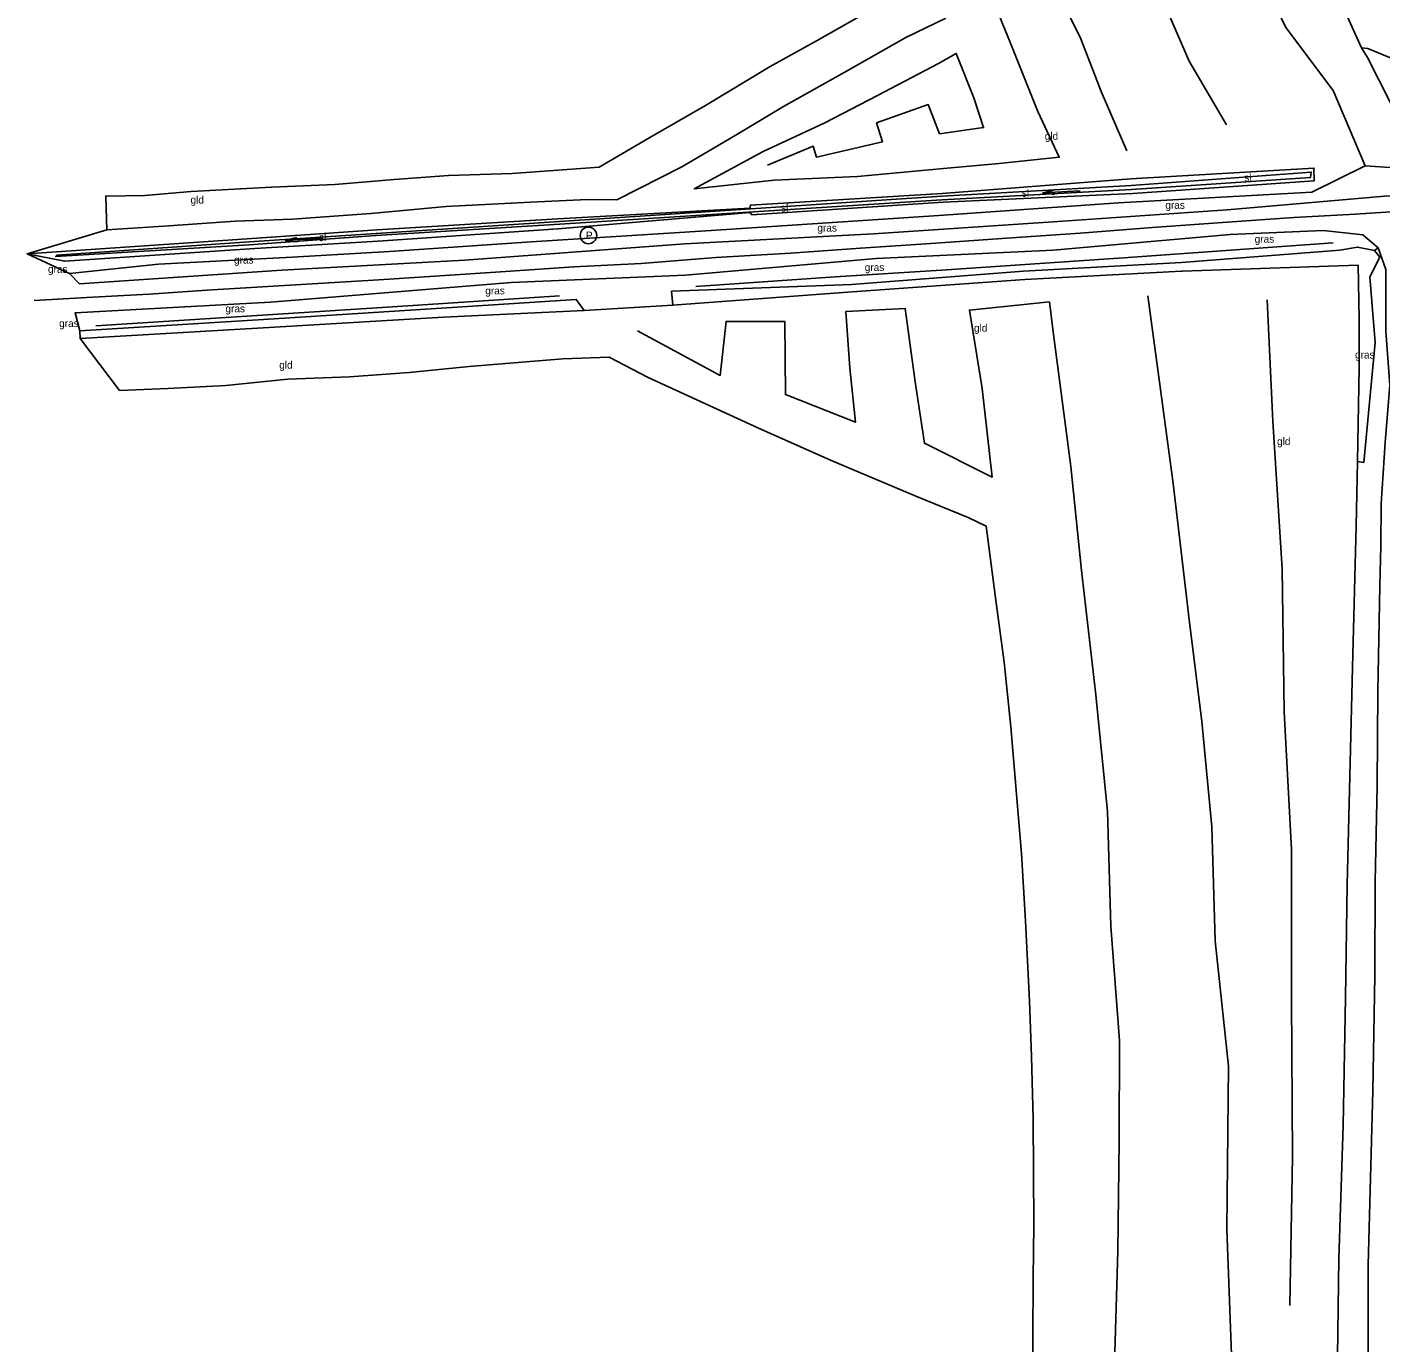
# Model space of a CAD drawing. Extents: x 154825 to 158680, y 370717 to 378075.
# Drawn here: x 156426.4 to 156606.6, y 375862.1 to 376037.2 of the extents above; entities that cross this region are included whole.
import ezdxf

# ---------------------------------------------------------------- set-up
doc = ezdxf.new("R2010")
doc.units = 0
for name, color, linetype in [('cultuurscheiding', 7, 'Continuous'), ('grasland_productiegrasl(vs)', 7, 'Continuous'), ('grazige vegetatie(vs)', 7, 'Continuous'), ('hoogteverschillijn', 7, 'Continuous'), ('insteek sloot', 7, 'Continuous'), ('maaiveldlijn algemeen - bomenrij', 7, 'Continuous'), ('maaiveldlijn algemeen - onverhard', 7, 'Continuous'), ('paal', 7, 'Continuous'), ('Sloot bodem', 7, 'Continuous'), ('sloot(vs)', 7, 'Continuous'), ('stroomrichting  watergangen', 7, 'Continuous'), ('talud(boven)', 7, 'Continuous'), ('talud(onder)', 7, 'Continuous'), ('vlak_Bos', 7, 'Continuous'), ('vlak_Grasland', 7, 'Continuous'), ('vlak_Grazige_vegetatie', 7, 'Continuous')]:
    doc.layers.add(name, color=color, linetype=linetype)

msp = doc.modelspace()

# ---------------------------------------------------------------- linework, layer by layer
at = {"layer": 'cultuurscheiding'}
for points in [[(156604.54, 376018.73), (156612.4, 376018.17)], [(156500.54, 375999.48), (156512.36, 376000.18)]]:
    msp.add_lwpolyline(points, dxfattribs=at)
at = {"layer": 'hoogteverschillijn'}
for points in [[(156572.81, 376020.7), (156569.38, 376028.63), (156566.66, 376035.61), (156562.66, 376043.74), (156558.89, 376051.97), (156554.33, 376061.88), (156550.91, 376068.69), (156549.14, 376076.18), (156546.72, 376083.8), (156543.62, 376095.48), (156540.86, 376103.26), (156537.96, 376111.44), (156532.62, 376123.33), (156528.05, 376133.6), (156524.15, 376142.59), (156520.35, 376150.68), (156516.56, 376158.36), (156513.06, 376167.53), (156508.88, 376177.28)], [(156521.01, 376174.48), (156526.43, 376162.47), (156529.26, 376156.81), (156535.53, 376142.49), (156540.79, 376129.18), (156547.42, 376112.95), (156551.02, 376105.12), (156555.68, 376094.87), (156558.92, 376084.45), (156563.58, 376070.67), (156570.02, 376056.98), (156576.17, 376044.06), (156581.09, 376032.64), (156586.08, 376024.16)], [(156554.59, 376041.68), (156557.33, 376035.04), (156560.94, 376025.97), (156563.79, 376019.86), (156555.81, 376019.01), (156548.37, 376018.35), (156536.94, 376017.28), (156525.83, 376016.81), (156515.22, 376015.65), (156524.37, 376020.63), (156532.58, 376024.45), (156539.59, 376028.08), (156547.73, 376032.32), (156550.09, 376033.68), (156552.45, 376027.78), (156553.73, 376023.81), (156547.86, 376022.99), (156546.36, 376026.87), (156539.49, 376024.42), (156540.26, 376021.89), (156531.48, 376019.88), (156531.05, 376021.33), (156524.96, 376018.8)], [(156539.14, 376039.72), (156531.59, 376035.39), (156525.3, 376031.93), (156516.7, 376026.74), (156509.3, 376022.5), (156502.55, 376018.53), (156490.99, 376017.72), (156482.51, 376017.43), (156475.25, 376016.91), (156467.36, 376016.23), (156458.94, 376015.89), (156448.24, 376015.32), (156442.1, 376014.76), (156436.88, 376014.69), (156437.02, 376010.22), (156445.26, 376010.73), (156454.1, 376011.34), (156461.72, 376011.62), (156472.16, 376012.38), (156482.17, 376013.31), (156493.42, 376013.88), (156501, 376014.22), (156504.89, 376014.19), (156513.54, 376018.57), (156520.67, 376022.77), (156527.08, 376026.62), (156535.16, 376031.13), (156543.38, 376035.78), (156548.72, 376038.38)], [(156604.88, 376034.31), (156610.79, 376031.88), (156617.32, 376029.23), (156621.46, 376027.63), (156624.69, 376026.73), (156632.63, 376026.83), (156642.28, 376027.82), (156651.67, 376028.35), (156659.22, 376028.61), (156666.15, 376029.34), (156673.91, 376029.82), (156685.81, 376030.47), (156685.94, 376026.48), (156678.99, 376025.48), (156670.4, 376025.46), (156664.83, 376024.91), (156657.65, 376024.69), (156650.29, 376024.51), (156641.83, 376024.02), (156632.93, 376023.17), (156624.09, 376022.6), (156617.93, 376022.16), (156612.67, 376024.46)], [(156427.36, 376000.79), (156435.16, 376001.23), (156442.65, 376001.65), (156450.32, 376002.19), (156473.24, 376003.53), (156480.69, 376004.02), (156490.08, 376004.65), (156499.18, 376005.27), (156508.15, 376005.73), (156518.1, 376006.5), (156528.04, 376007.11), (156537.36, 376007.78), (156547.35, 376008.42), (156556.81, 376009.08), (156566.6, 376009.74), (156576.22, 376010.52), (156585.55, 376011.16), (156595.04, 376011.84), (156603.2, 376012.28), (156612.73, 376012.91)], [(156575.57, 376001.43), (156577.26, 375988.97), (156578.96, 375976.43), (156581.11, 375958.35), (156582.78, 375944.78), (156584.12, 375930.78), (156584.54, 375915.59), (156586.31, 375898.91), (156586.09, 375877.23), (156586.8, 375858.13), (156586.79, 375839.49), (156586.62, 375822.23), (156586.22, 375803.72), (156585.44, 375775.48), (156585.17, 375755.87), (156585.34, 375731.27), (156585.3, 375705.98), (156584.63, 375684.03)], [(156571.14, 375859.31), (156571.58, 375874.28), (156571.79, 375888.99), (156571.83, 375902.32), (156570.66, 375917.55), (156570.23, 375932.86), (156568.61, 375948.72), (156566.77, 375964.85), (156565.34, 375978.7), (156562.97, 375996.65), (156562.5, 376000.6), (156551.83, 375999.53), (156553.54, 375989.11), (156554.87, 375977.3), (156545.86, 375981.8), (156544.64, 375989.98), (156543.28, 375999.74), (156535.38, 375999.32), (156535.93, 375991.8), (156536.66, 375984.6), (156527.35, 375988.28), (156527.26, 375998.01), (156519.45, 375998.01), (156518.68, 375990.83), (156507.68, 375996.78)], [(156591.46, 376000.9), (156592.25, 375984.75), (156593.49, 375965.08), (156593.73, 375946.05), (156594.73, 375927.73), (156594.73, 375907.83), (156594.85, 375886.86), (156594.5, 375867.08)], [(156438.73, 375988.81), (156445.14, 375989.08), (156452.86, 375989.49), (156461.12, 375990.35), (156469.31, 375990.63), (156477.25, 375991.22), (156485.27, 375992.02), (156497.7, 375993.04), (156503.88, 375993.25), (156509.09, 375990.55), (156523.67, 375983.84), (156533.33, 375979.56), (156544.73, 375974.78), (156551.67, 375971.92), (156554.06, 375970.77), (156555.39, 375960.55), (156556.48, 375952.68), (156557.35, 375944.05), (156558.33, 375932.44), (156558.79, 375927.23), (156559.32, 375918.22), (156559.85, 375907.59), (156560.1, 375900.22), (156560.34, 375891.92), (156560.42, 375877.81), (156560.33, 375870.69), (156560.3, 375862.63), (156560.23, 375856.26)]]:
    msp.add_lwpolyline(points, dxfattribs=at)
at = {"layer": 'insteek sloot'}
msp.add_lwpolyline([(156597.7, 376018.42), (156573.34, 376017), (156548.2, 376015.05), (156522.69, 376013.5), (156522.61, 376013.07), (156497.05, 376011.67), (156473.02, 376010.19), (156454.42, 376008.93), (156426.41, 376007.02), (156431.41, 376006.03), (156456.72, 376007.74), (156473.14, 376008.68), (156497.04, 376010.32), (156522.65, 376012.52), (156522.9, 376012.2), (156548.36, 376013.87), (156573.59, 376015.05), (156597.71, 376016.71), (156597.7, 376018.42)], dxfattribs=at)
at = {"layer": 'maaiveldlijn algemeen - bomenrij'}
for points in [[(156604.85, 376033.15), (156604.03, 376034.4), (156598.81, 376046.03), (156593.52, 376057.34), (156586.98, 376071.77), (156581.55, 376083.58), (156576.24, 376095.35), (156568.66, 376112.12), (156562.27, 376126.6), (156550.14, 376152.66), (156543.83, 376166.91), (156537.32, 376180.85), (156530.37, 376196.59), (156518.98, 376222.43), (156509.87, 376242.4), (156507.27, 376248.14), (156501.91, 376260.01), (156498.71, 376267.58)], [(156503.91, 376232.79), (156504.98, 376231.61), (156514.5, 376210.59), (156527.1, 376182.74), (156537.65, 376159.52), (156549.71, 376132.58), (156562.03, 376105.32), (156575.26, 376075.98), (156593.98, 376037.13), (156600.26, 376028.74), (156604.54, 376018.73), (156597.43, 376015.23), (156571.68, 376013.78), (156547.77, 376012.12), (156517.45, 376010.13), (156493.51, 376008.61), (156474.64, 376007.3), (156461.67, 376006.58), (156443.92, 376005.62), (156432.05, 376004.41)], [(156693.04, 376021.31), (156667.6, 376019.69), (156643.66, 376018.26), (156619.44, 376016.89), (156612.4, 376018.17), (156604.85, 376033.15), (156604.03, 376034.4)], [(156600.27, 376008.48), (156572.37, 376006.48), (156548.11, 376004.85), (156533.98, 376003.94), (156515.43, 376002.64)], [(156497.26, 376001.44), (156475.05, 375999.96), (156435.54, 375997.41)], [(156603.48, 375979.36), (156603.32, 375970.76), (156602.84, 375951.94), (156602.12, 375923.05), (156601.9, 375908.04), (156601.61, 375891.01), (156601, 375873.29), (156600.65, 375847.27), (156600.46, 375831.64), (156600.18, 375815.71), (156599.28, 375767.14), (156599.09, 375748.37), (156598.64, 375715.86), (156598.42, 375698.91), (156598.97, 375673.82)]]:
    msp.add_lwpolyline(points, dxfattribs=at)
at = {"layer": 'maaiveldlijn algemeen - onverhard'}
for points in [[(156433.39, 376003.01), (156460.31, 376004.82), (156484.66, 376006.15), (156513.94, 376008.36), (156539.09, 376009.68), (156563.01, 376011.28), (156586.14, 376012.86), (156607.15, 376014.69), (156622.62, 376015.22), (156644.34, 376016.34), (156693.74, 376020.07)], [(156432.8, 375999.17), (156458.8, 376000.56), (156490.83, 376003.18), (156514.06, 376004.16), (156539.42, 376006.39), (156562.97, 376007.51), (156586.55, 376009.57), (156598.96, 376010.13), (156604.22, 376009.52), (156606.24, 376007.8), (156607.29, 376004.92), (156607.27, 375996.72), (156607.79, 375989.55), (156607.16, 375981.92)], [(156604.91, 375859.72), (156604.93, 375872.44), (156605.52, 375895.64), (156605.8, 375910.92), (156605.85, 375923.43), (156606.12, 375936.28), (156606.21, 375948.78), (156606.49, 375962.82), (156606.61, 375968.16), (156606.64, 375973.76), (156607.16, 375981.92)]]:
    msp.add_lwpolyline(points, dxfattribs=at)
at = {"layer": 'paal'}
msp.add_circle((156501.13, 376009.46), 1.1, dxfattribs=at)
at = {"layer": 'Sloot bodem'}
msp.add_lwpolyline([(156597.34, 376017.89), (156573.36, 376016.11), (156548.17, 376014.68), (156496.61, 376011.28), (156472.89, 376009.71), (156455.97, 376008.6), (156430.37, 376006.82), (156430.2, 376006.65), (156455.97, 376008.2), (156472.82, 376009.45), (156496.63, 376010.89), (156548.17, 376014.18), (156573.43, 376015.57), (156597.23, 376017.17), (156597.34, 376017.89)], dxfattribs=at)
at = {"layer": 'stroomrichting  watergangen'}
for p, q in [((156561.59, 376015.14), (156563.13, 376015.49)), ((156566.58, 376015.37), (156561.59, 376015.14)), ((156561.61, 376015.13), (156563.18, 376014.92)), ((156460.78, 376008.82), (156462.32, 376009.16)), ((156465.77, 376009.05), (156460.78, 376008.82)), ((156460.8, 376008.8), (156462.36, 376008.6))]:
    msp.add_line(p, q, dxfattribs=at)
at = {"layer": 'talud(boven)'}
for points in [[(156512.19, 376002.03), (156536.15, 376002.92), (156559.04, 376004.72), (156580.08, 376005.86), (156601.14, 376007.49), (156603.52, 376007.91), (156605.75, 376007.47), (156606.48, 376006.57), (156605.16, 376003.94), (156605.85, 375995.23), (156604.34, 375979.25)], [(156433.44, 375996.78), (156458.6, 375998.32), (156481.56, 375999.8), (156499.5, 376000.91)]]:
    msp.add_lwpolyline(points, dxfattribs=at)
at = {"layer": 'talud(onder)'}
for points in [[(156512.36, 376000.18), (156536.23, 376001.97), (156559.21, 376003.6), (156580.06, 376004.7), (156580.15, 376004.7), (156603.6, 376005.48), (156603.7, 375998.36), (156603.73, 375991.89), (156603.48, 375979.36)], [(156512.36, 376000.18), (156512.19, 376002.03)], [(156500.54, 375999.48), (156499.5, 376000.91)], [(156433.44, 375996.78), (156433.46, 375995.74), (156458.57, 375997.2), (156481.84, 375998.59), (156500.54, 375999.48)], [(156604.34, 375979.25), (156603.48, 375979.36)]]:
    msp.add_lwpolyline(points, dxfattribs=at)
at = {"layer": 'vlak_Bos'}
for points in [[(156537.32, 376180.85), (156543.83, 376166.91), (156550.14, 376152.66), (156562.27, 376126.6), (156568.66, 376112.12), (156576.24, 376095.35), (156581.55, 376083.58), (156586.98, 376071.77), (156593.52, 376057.34), (156598.81, 376046.03), (156604.03, 376034.4), (156604.85, 376033.15), (156612.4, 376018.17), (156604.54, 376018.73), (156600.26, 376028.74), (156593.98, 376037.13), (156575.26, 376075.98), (156562.03, 376105.32), (156549.71, 376132.58), (156537.65, 376159.52), (156527.1, 376182.74)], [(156600.65, 375847.27), (156601, 375873.29), (156601.61, 375891.01), (156601.9, 375908.04), (156602.12, 375923.05), (156602.84, 375951.94), (156603.32, 375970.76), (156603.48, 375979.36), (156604.34, 375979.25), (156605.85, 375995.23), (156605.16, 376003.94), (156606.48, 376006.57), (156605.75, 376007.47), (156606.24, 376007.8), (156607.29, 376004.92)], [(156606.64, 375973.76), (156606.61, 375968.16), (156606.49, 375962.82), (156606.21, 375948.78), (156606.12, 375936.28), (156605.85, 375923.43), (156605.8, 375910.92), (156605.52, 375895.64), (156604.93, 375872.44), (156604.91, 375859.72)]]:
    msp.add_lwpolyline(points, dxfattribs=at)
at = {"layer": 'vlak_Grasland'}
for points in [[(156575.26, 376075.98), (156593.98, 376037.13), (156600.26, 376028.74), (156604.54, 376018.73), (156597.43, 376015.23), (156571.68, 376013.78), (156547.77, 376012.12), (156517.45, 376010.13), (156493.51, 376008.61), (156474.64, 376007.3), (156461.67, 376006.58), (156443.92, 376005.62), (156432.05, 376004.41), (156426.41, 376007.02), (156431.41, 376006.03), (156456.72, 376007.74), (156473.14, 376008.68), (156497.04, 376010.32), (156522.65, 376012.52), (156522.9, 376012.2), (156548.36, 376013.87), (156573.59, 376015.05), (156597.71, 376016.71), (156597.7, 376018.42), (156573.34, 376017), (156548.2, 376015.05), (156522.69, 376013.5), (156522.61, 376013.07), (156497.05, 376011.67), (156473.02, 376010.19), (156454.42, 376008.93), (156426.41, 376007.02), (156437.02, 376010.22), (156436.88, 376014.69), (156442.1, 376014.76), (156448.24, 376015.32), (156458.94, 376015.89), (156467.36, 376016.23), (156475.25, 376016.91), (156482.51, 376017.43), (156490.99, 376017.72), (156502.55, 376018.53), (156509.3, 376022.5), (156516.7, 376026.74), (156525.3, 376031.93), (156531.59, 376035.39), (156539.14, 376039.72)], [(156560.23, 375856.26), (156560.3, 375862.63), (156560.33, 375870.69), (156560.42, 375877.81), (156560.34, 375891.92), (156560.1, 375900.22), (156559.85, 375907.59), (156559.32, 375918.22), (156558.79, 375927.23), (156558.33, 375932.44), (156557.35, 375944.05), (156556.48, 375952.68), (156555.39, 375960.55), (156554.06, 375970.77), (156551.67, 375971.92), (156544.73, 375974.78), (156533.33, 375979.56), (156523.67, 375983.84), (156509.09, 375990.55), (156503.88, 375993.25), (156497.7, 375993.04), (156485.27, 375992.02), (156477.25, 375991.22), (156469.31, 375990.63), (156461.12, 375990.35), (156452.86, 375989.49), (156445.14, 375989.08), (156438.73, 375988.81), (156433.46, 375995.74), (156458.57, 375997.2), (156481.84, 375998.59), (156500.54, 375999.48), (156512.36, 376000.18), (156536.23, 376001.97), (156559.21, 376003.6), (156580.06, 376004.7), (156580.15, 376004.7), (156603.6, 376005.48), (156603.7, 375998.36), (156603.73, 375991.89), (156603.48, 375979.36), (156603.32, 375970.76), (156602.84, 375951.94), (156602.12, 375923.05), (156601.9, 375908.04), (156601.61, 375891.01), (156601, 375873.29), (156600.65, 375847.27)]]:
    msp.add_lwpolyline(points, dxfattribs=at)
msp.add_lwpolyline([(156621.46, 376027.63), (156624.69, 376026.73), (156632.63, 376026.83), (156642.28, 376027.82), (156651.67, 376028.35), (156659.22, 376028.61), (156666.15, 376029.34), (156673.91, 376029.82), (156685.81, 376030.47), (156685.94, 376026.48), (156691.91, 376023.08), (156692.61, 376022.08), (156693.04, 376021.31), (156667.6, 376019.69), (156643.66, 376018.26), (156619.44, 376016.89), (156612.4, 376018.17), (156604.85, 376033.15), (156604.03, 376034.4), (156604.88, 376034.31), (156610.79, 376031.88), (156617.32, 376029.23)], close=True, dxfattribs=at)
at = {"layer": 'vlak_Grazige_vegetatie'}
for points in [[(156597.7, 376018.42), (156597.71, 376016.71), (156573.59, 376015.05), (156548.36, 376013.87), (156522.9, 376012.2), (156522.65, 376012.52), (156497.04, 376010.32), (156473.14, 376008.68), (156456.72, 376007.74), (156431.41, 376006.03), (156426.41, 376007.02), (156454.42, 376008.93), (156473.02, 376010.19), (156497.05, 376011.67), (156522.61, 376013.07), (156522.69, 376013.5), (156548.2, 376015.05), (156573.34, 376017)], [(156430.37, 376006.82), (156430.2, 376006.65), (156455.97, 376008.2), (156472.82, 376009.45), (156496.63, 376010.89), (156548.17, 376014.18), (156573.43, 376015.57), (156597.23, 376017.17), (156597.34, 376017.89), (156573.36, 376016.11), (156548.17, 376014.68), (156496.61, 376011.28), (156472.89, 376009.71), (156455.97, 376008.6)], [(156604.22, 376009.52), (156606.24, 376007.8), (156605.75, 376007.47), (156603.52, 376007.91), (156601.14, 376007.49), (156580.08, 376005.86), (156559.04, 376004.72), (156536.15, 376002.92), (156512.19, 376002.03), (156512.36, 376000.18), (156500.54, 375999.48), (156499.5, 376000.91), (156481.56, 375999.8), (156458.6, 375998.32), (156433.44, 375996.78), (156432.8, 375999.17), (156458.8, 376000.56), (156490.83, 376003.18), (156514.06, 376004.16), (156539.42, 376006.39), (156562.97, 376007.51), (156586.55, 376009.57), (156598.96, 376010.13)], [(156606.48, 376006.57), (156605.16, 376003.94), (156605.85, 375995.23), (156604.34, 375979.25), (156603.48, 375979.36), (156603.73, 375991.89), (156603.7, 375998.36), (156603.6, 376005.48), (156580.15, 376004.7), (156580.06, 376004.7), (156559.21, 376003.6), (156536.23, 376001.97), (156512.36, 376000.18), (156512.19, 376002.03), (156536.15, 376002.92), (156559.04, 376004.72), (156580.08, 376005.86), (156601.14, 376007.49), (156603.52, 376007.91), (156605.75, 376007.47)], [(156458.57, 375997.2), (156433.46, 375995.74), (156433.44, 375996.78), (156458.6, 375998.32), (156481.56, 375999.8), (156499.5, 376000.91), (156500.54, 375999.48), (156481.84, 375998.59)]]:
    msp.add_lwpolyline(points, close=True, dxfattribs=at)
msp.add_lwpolyline([(156607.15, 376014.69), (156586.14, 376012.86), (156563.01, 376011.28), (156539.09, 376009.68), (156513.94, 376008.36), (156484.66, 376006.15), (156460.31, 376004.82), (156433.39, 376003.01), (156432.05, 376004.41), (156443.92, 376005.62), (156461.67, 376006.58), (156474.64, 376007.3), (156493.51, 376008.61), (156517.45, 376010.13), (156547.77, 376012.12), (156571.68, 376013.78), (156597.43, 376015.23), (156604.54, 376018.73), (156612.4, 376018.17)], dxfattribs=at)

# ---------------------------------------------------------------- texts
at = {"layer": 'grasland_productiegrasl(vs)'}
for p in [(156561.87, 376022.19), (156448.16, 376013.7), (156552.45, 375996.65), (156459.97, 375991.73), (156592.79, 375981.56)]:
    msp.add_text('gld', height=1, dxfattribs=at).set_placement(p)
at = {"layer": 'grazige vegetatie(vs)'}
for p in [(156577.92, 376013), (156531.6, 376009.97), (156589.81, 376008.49), (156429.19, 376004.48), (156453.95, 376005.71), (156537.91, 376004.72), (156487.4, 376001.61), (156452.81, 375999.23), (156430.67, 375997.26), (156603.17, 375993.08)]:
    msp.add_text('gras', height=1, dxfattribs=at).set_placement(p)
at = {"layer": 'paal'}
msp.add_text('P', height=1, dxfattribs=at).set_placement((156500.8, 376008.96))
at = {"layer": 'sloot(vs)'}
for p in [(156588.42, 376016.65), (156558.82, 376014.6), (156526.77, 376012.63), (156465.27, 376008.7)]:
    msp.add_text('sl', height=1, dxfattribs=at).set_placement(p)

doc.saveas('drawing.dxf')
